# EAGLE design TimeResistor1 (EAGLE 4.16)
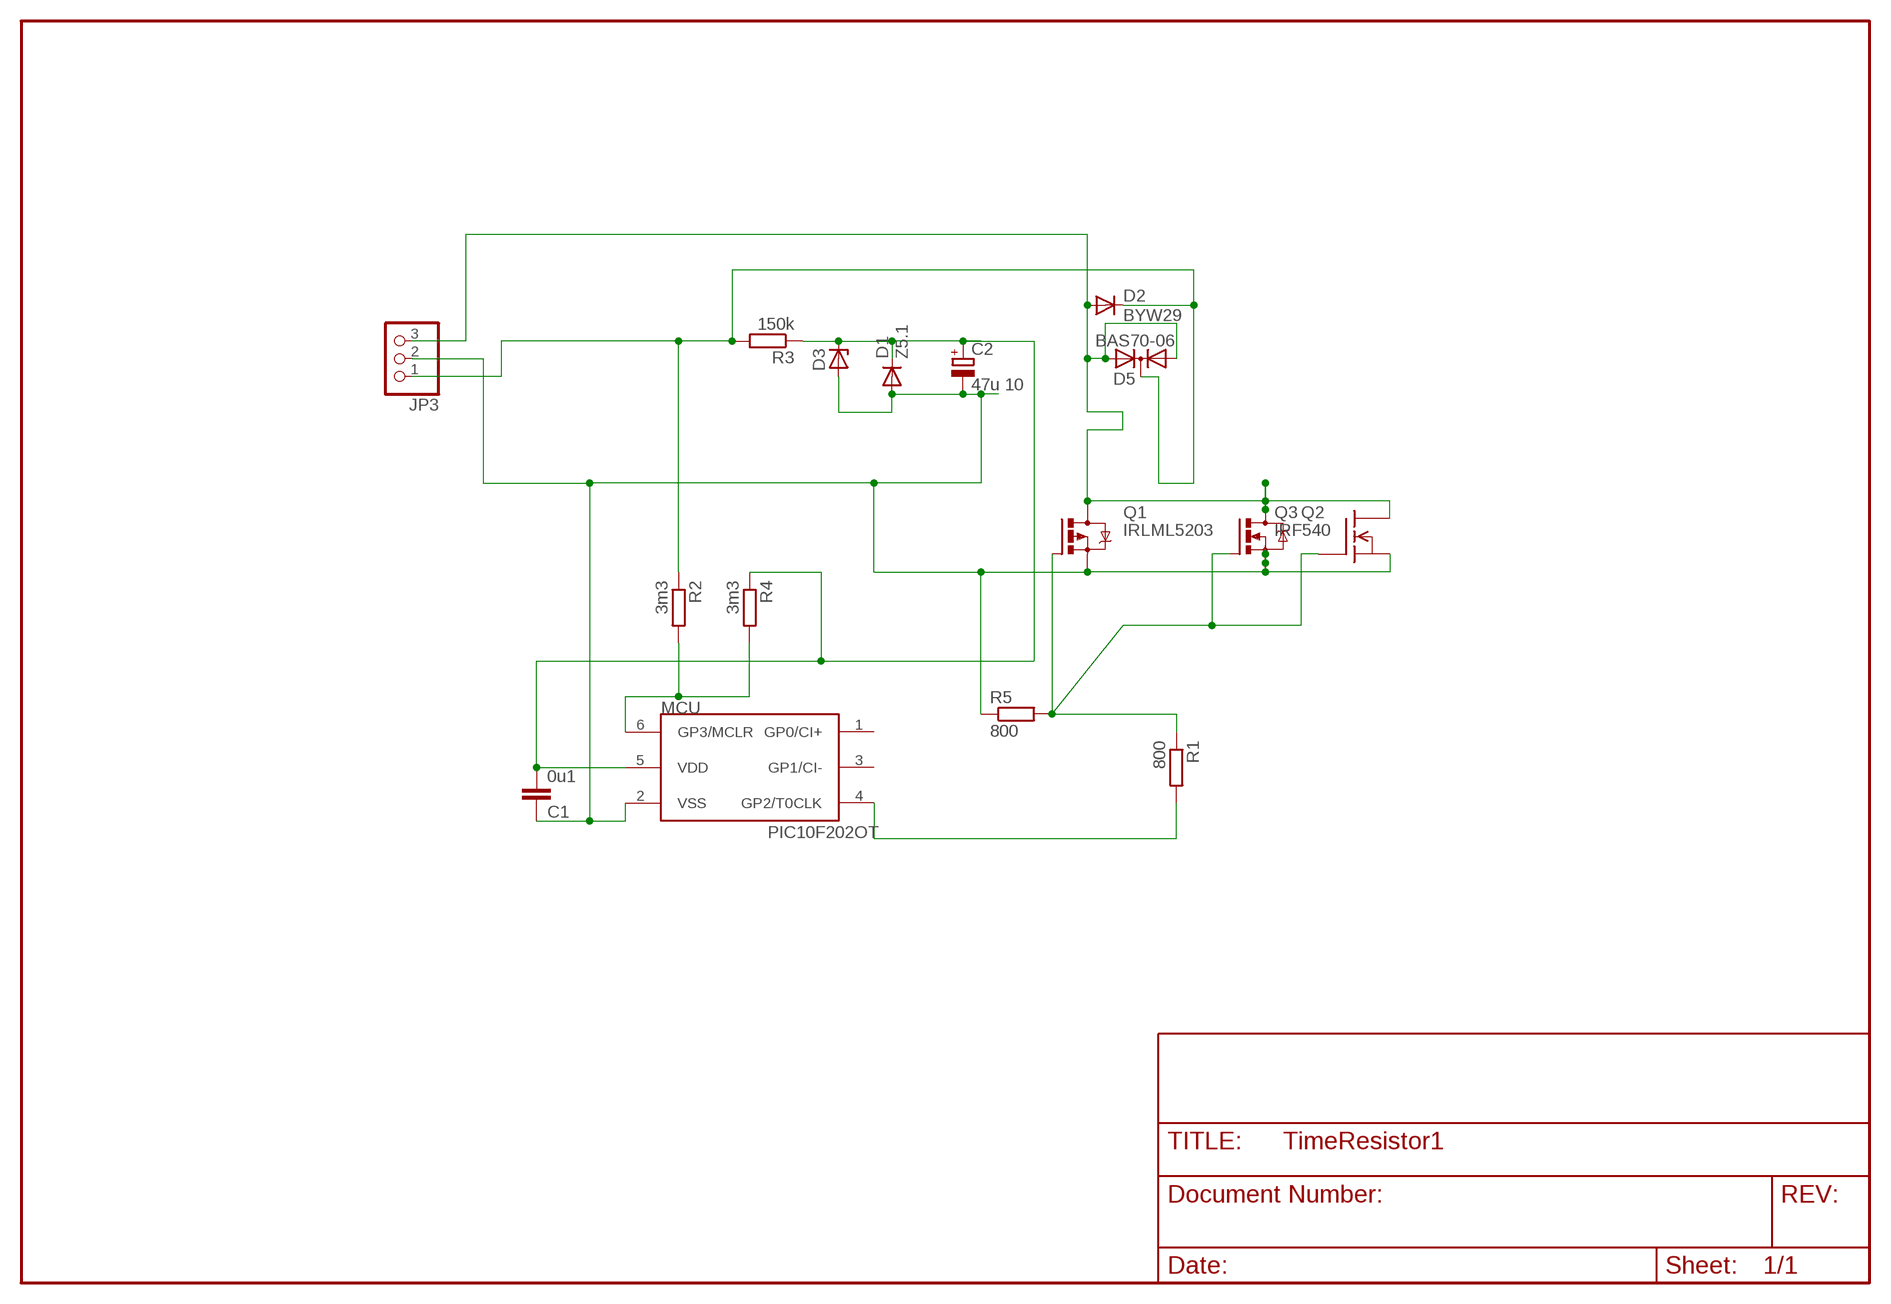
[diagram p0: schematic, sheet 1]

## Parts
C1  0u1  C-EUC1206  [C1206]
C2  47u 10  CPOL-EUSMCD  [SMC_D]
D1  Z5.1  DIODE-MINIMELF  [MINIMELF]
D2  BYW29  [DO220S]
D3  ZENER-DIODESOT23  [SOT23]
D5  BAS70-06  [SOT23]
JP3  PINHD-1X3  [1X03]
MCU  PIC10F202OT  [SOT23-6]
Q1  IRLML5203  [MICRO3]
Q2  N-MOSFET-SO8S  [SO-08]
Q3  IRF540  [TO220]
R1  800  R-EU_R1206  [R1206]
R2  3m3  R-EU_R1206  [R1206]
R3  150k  R-EU_R1206  [R1206]
R4  3m3  R-EU_R1206  [R1206]
R5  800  R-EU_R1206  [R1206]

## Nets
N$1: Q1.1(G) Q2.4(G) Q3.1(G) R1.1 R5.2
N$2: D2.A D5.1(A1) D5.2(A2) JP3.3 Q1.3(D) Q2.5(D) Q2.7(D) Q2.8(D) Q3.2(D)
N$8: C1.1 C2.- D1.A D3.1(A) JP3.2 MCU.2(VSS) Q1.2(S) Q2.1(S) Q2.2(S) Q2.3(S) Q3.3(S) R5.1
N$9: D2.C D5.3(C) JP3.1 R2.1 R3.2
N$12: MCU.6(GP3/MCLR) R2.2 R4.2
N$14: MCU.4(GP2/T0CLK) R1.2
V2CC: C1.2 C2.+ D1.C D3.3(C) MCU.5(VDD) R3.1 R4.1
Unconnected: MCU.1(GP0/CI+) MCU.3(GP1/CI-) Q2.6(D)

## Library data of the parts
C1 = rcl:C-EU: CAPACITOR, European symbol
C2 = rcl:CPOL-EU: POLARIZED CAPACITOR, European symbol
D1 = diode:DIODE-: DIODE
D2 = diode:BYW29: DIODE
D3 = diode-1:ZENER-DIODE: Z-Diode
D5 = diode:BAS70-06: Silicon Schottky Diodes General-purpose diode for high-speed switching
JP3 = pinhead:PINHD-1X3: PIN HEADER
MCU = microchip-3:PIC10F2*: uPC nW 0,25/0,5k Program Flash memory Comparator
Q1 = transistor-power:IRLML5203: HEXFET P-Channel Power MOSFET
Q2 = transistor-power:N-MOSFET-SO8: N-Channel MOSFET Example: FDS7760A; N-Channel Logic Level PowerTrench® MOSFET FDS2572; N-Channel UltraFET® Trench MOSFET Source: www.fairchildsemi.com
Q3 = transistor-fet+irf7201:IRF540: N-Channel Enhancement MOSFET (HEXFET); 100V; 28A; 0,077Ohm
R1-R5 = rcl:R-EU_: RESISTOR, European symbol

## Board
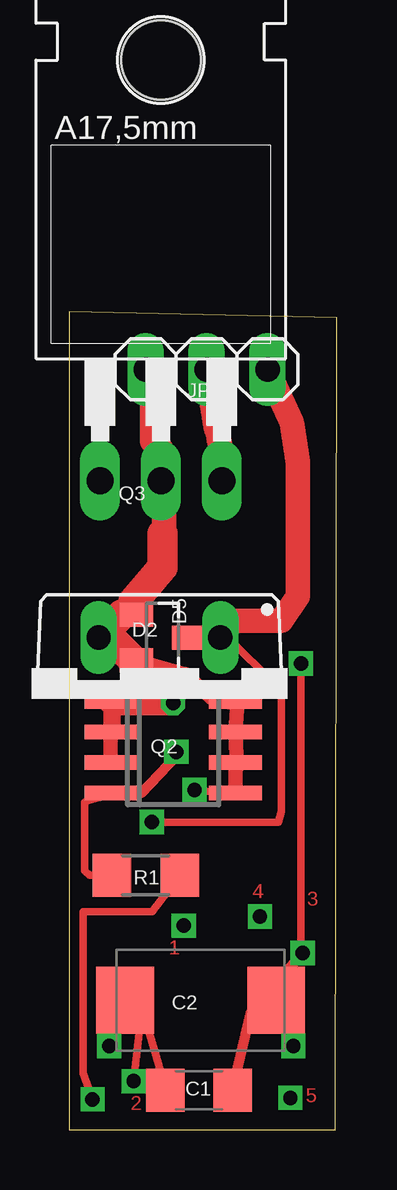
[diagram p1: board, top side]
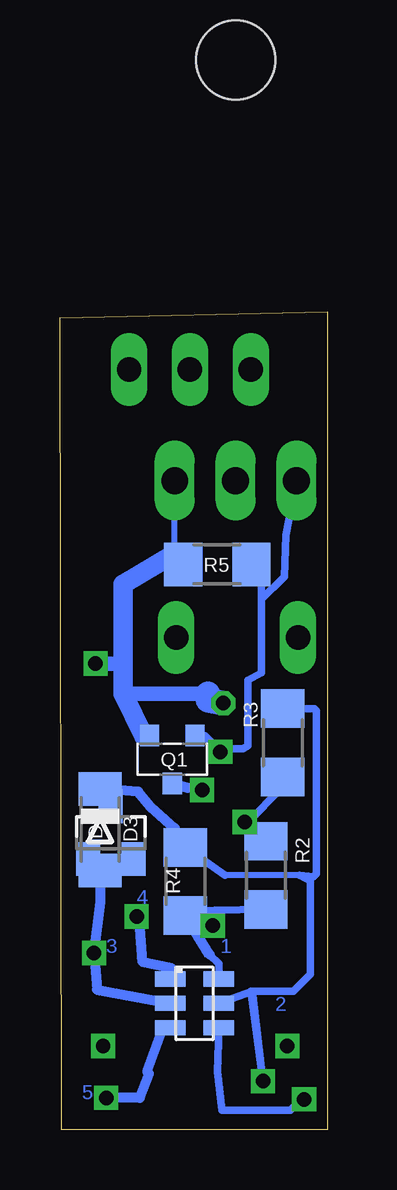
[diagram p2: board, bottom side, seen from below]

Size 11.16 x 34.09 mm. Coordinates in mm from the lower left corner, seen from the top.
Outline: 0,0 11.1,0 11.16,33.84 0,34.09 0,0
Copper layers (1*16): Top 0.035mm / dielectric 1.5mm / Bottom 0.035mm
Design rules "default": minimum track width 10mil, minimum drill 24mil, track to track 8mil, track to pad 8mil, pad to pad 8mil, via to via 8mil, smd to smd 8mil, copper to edge 40mil, drill to drill 8mil, minimum pad ring 10mil, minimum via ring 8mil, stop-mask expansion 4mil, vias tented up to drill 0mil, thermal gap 10mil

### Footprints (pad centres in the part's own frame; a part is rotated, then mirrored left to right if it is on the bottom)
C1206 = smd 1.6 x 1.8: 1 -1.4,0; 2 1.4,0
SMC_D = smd 2.4 x 2.8: + -3.15,0; - 3.15,0
MINIMELF = smd 1.4 x 1.8: A 1.7,0; C -1.7,0
DO220S = drill 1.016 long: A 2.54,-2.54; C -2.54,-2.54
SOT23 = smd 1 x 1.4: 1 -0.95,-1.1; 2 0.95,-1.1; 3 0,1.1
1X03 = drill 1.016 long: 1 -2.54,0; 2 0,0; 3 2.54,0
SOT23-6 = smd 0.635 x 1.27: 1 -1.016,-1.016; 2 0,-1.016; 3 1.016,-1.016; 4 1.016,1.016; 5 0,1.016; 6 -1.016,1.016
MICRO3 = smd 0.8 x 0.9: 1 -0.95,-1; 2 0.95,-1; 3 0,1
SO-08 = smd 0.6 x 2.2: 1 -1.905,-2.6; 2 -0.635,-2.6; 3 0.635,-2.6; 4 1.905,-2.6; 5 1.905,2.6; 6 0.635,2.6; 7 -0.635,2.6; 8 -1.905,2.6
TO220 = drill 1.118 long: 1 -2.54,-6.35; 2 0,-6.35; 3 2.54,-6.35 | hole 3.302: 0,11.176
R1206 = smd 1.6 x 1.803: 1 -1.422,0; 2 1.422,0

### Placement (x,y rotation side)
C1  5.42,1.65 180 top
C2  5.49,5.39 0 top
D1  9.49,12.5 270 bottom
D2  3.77,17.97 180 top
D3  9.04,12.38 0 bottom
D5  3.9,20.51 270 top
JP3  5.74,31.68 180 top
MCU  5.55,5.27 270 bottom
Q1  6.47,15.43 180 bottom
Q2  4.34,15.93 270 top
Q3  3.84,33.4 0 top
R1  3.2,10.6 0 top
R2  2.57,10.6 270 bottom
R3  1.87,16.12 270 bottom
R4  5.93,10.35 270 bottom
R5  4.6,23.55 0 bottom

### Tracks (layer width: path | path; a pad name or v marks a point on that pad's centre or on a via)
N$1  (via drill 0.6)
  Top 0.254: 2.57,13.84 Q2.4 1.3,13.84 0.66,13.65
  Top 0.305: 0.66,13.65 0.66,10.79 0.85,10.6 1.68,10.6 1.78,10.7 R1.1 | 4.41,15.62 4.34,15.68
  Top 0.406: Q2.4 3.01,14.03 4.53,15.62 v4.47,15.74 arc254 4.41,15.62
  Bottom 0.254: 5.12,16.36 5.11,16.38
  Bottom 0.305: 2.76,22.09 1.8,23.05 1.74,24.76 Q3.1 1.3,26.98 | 5.12,16.36 5.45,16.57 5.55,16.63 | 2.76,22.09 2.76,19.05 3.33,18.73 3.33,16 3.52,15.87 4.28,15.87 4.47,15.68 v4.47,15.74 | R5.2 3.14,23.43 2.76,23.05 2.76,22.09
  Bottom 0.406: v4.47,15.74 4.6,15.81 5.12,16.36 | 5.45,16.57 5.49,16.51 Q1.1
N$2  (via drill 0.6)
  Top 0.305: Q2.7 Q2.8 6.94,17.78 6.95,17.78 | 6.95,15.04 7.01,15.1 | 7.01,17.52 6.95,17.59 | 3.96,24.95 3.9,24.82 4.15,24.89 | D5.1 2.8,21.44 2.69,21.33 2.69,22.03 | D2.A 1.3,20.63 2.12,21.46 D5.1 | 2.18,21.46 D5.1 | 2.82,19.43 2.8,19.45 D5.2 | 1.61,20.63 1.36,20.63 | 5.17,14.09 v5.23,14.16 6.88,13.96 Q2.5
  Top 0.61: Q2.5 6.95,15.04 | 7.01,15.1 Q2.7 7.01,17.52 | D5.2 4.85,18.98 5.55,18.35 6.06,17.9 6.94,17.78
  Top 1.016: 3.96,24.95 3.96,27.05 3.84,27.17 Q3.2 3.84,28.38 3.45,28.7 3.45,31.43 3.26,31.68 JP3.3
  Top 1.27: 3.9,24.82 3.9,23.43 2.69,22.03 | 1.36,20.63 2.18,21.46 | 2.8,19.45 1.61,20.63
  Bottom 0.305: 5.83,14.24 v5.23,14.16
  Bottom 0.406: Q1.3 5.83,14.24
N$3  (via drill 0.6)
  other vias: 4.79,8.5
N$4  (via drill 0.6)
  Bottom 0.254: v9.23,1.33 8.92,1.27 8.91,1.33
  Bottom 0.406: 7.45,2.34 7.84,1.33 8.91,1.33 8.98,1.33
N$5  (via drill 0.6)
  Bottom 0.254: v7.96,8.88 7.65,8.76 7.84,8.69
  Bottom 0.406: 6.5,6.73 7.71,6.98 7.84,8.69
N$6
  Top 0.406: 6.88,2.34 7.39,2.34
N$7
  Bottom 0.406: 7.52,2.41 6.88,4.19
N$8  (via drill 0.6)
  Top 0.305: v9.74,7.36 9.68,7.87 v9.68,19.43
  Top 0.406: C1.1 7.58,4.88 8.53,6.28 C2.- 9.23,6.79 v9.74,7.36 9.74,7.49
  Top 0.61: Q3.3 6.44,27.05 6.44,26.98 | Q2.1 1.74,17.9 | 1.74,17.9 Q2.2 | Q2.2 Q2.3 | 1.74,17.9 | Q2.2 1.8,16.51 1.87,16.57 1.87,17.78
  Top 1.016: 6.12,29.21 JP3.2 6.38,28.06 | Q2.1 1.8,17.84 1.87,17.78 v4.34,17.78
  Top 1.27: 6.44,26.98 6.38,28.06
  Bottom 0.254: 7.65,16.38 Q1.2 | 6.38,24 Q3.3
  Bottom 0.305: D1.A 9.5,10.8 9.97,11.28 D3.1 9.78,11.28 9.74,11.23 | 6.42,23.98 6.44,24 | 6.42,23.97 6.42,23.98 | R5.1 6.02,23.58 6.42,23.98
  Bottom 0.406: D1.A 9.47,9.47 v9.74,7.36 9.61,5.84 MCU.2
  Bottom 0.61: 8.53,18.16 4.98,18.16 | v9.68,19.43 8.53,19.43
  Bottom 0.813: 7.65,16.38 8.53,18.16 8.53,19.43 8.53,22.73 6.42,23.97 6.38,24
  Bottom 1.016: 4.98,18.16 4.98,17.9 v4.34,17.78
N$9  (via drill 0.6)
  Top 0.305: D5.3 6.06,20.51 6.25,20.7 D2.C 6.31,20.7 6.38,20.76 8.85,18.28 8.85,13.27 8.73,12.82 v3.45,12.82
  Top 1.016: JP3.1 9.3,29.46 9.55,27.81 9.55,22.22 8.85,21.2 6.63,21.2 6.31,20.89 D2.C
  Bottom 0.305: R2.1 2.65,12.02 3.39,12.76 | 3.39,12.76 v3.45,12.82 | R3.2 1.87,14.28 3.39,12.76
N$10  (via drill 0.6)
  other vias: 1.68,3.49
N$11  (via drill 0.6)
  other vias: 9.36,3.49
N$12
  Bottom 0.305: MCU.6 4.53,6.92 4.91,7.3 | R4.2 6.1,8.92 6.06,8.88 5.83,9.11 R2.2
  Bottom 0.406: 4.91,7.3 R4.2
N$14  (via drill 0.6)
  Top 0.305: R1.2 3.45,9.08 0.6,9.08 0.6,2.34 v0.98,1.27
  Bottom 0.305: MCU.4 4.6,2.41 4.41,0.82 1.55,0.82 1.1,1.27 v0.98,1.27
V2CC  (via drill 0.6)
  Top 0.305: C1.2 3.9,2.16 2.91,5.48 2.88,5.58 | 2.88,5.58 2.57,5.9 | v2.69,2.03 3.14,5.84 2.88,5.58
  Top 0.406: 2.91,5.48 2.63,5.48 2.63,5.39 C2.+
  Bottom 0.254: 1.17,10.6 4.28,10.6 | 6.38,12.57 6.06,11.74 R4.1
  Bottom 0.305: MCU.5 3.14,5.77 v2.69,2.03 3.2,5.77 1.42,5.77 0.72,6.47 0.72,10.35 1.17,10.6 0.6,10.54 0.47,10.66 0.47,17.46 0.56,17.55 R3.1 | 4.28,10.6 R4.1 | D3.3 9.04,13.46 9.11,13.39 9.49,13.77 D1.C
  Bottom 0.406: 6.38,12.57 7.39,13.46 7.9,14.09 D1.C

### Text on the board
Top: 4 | 3 | 1 | 2 | 5
Bottom: 4 | 1 | 3 | 2 | 5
